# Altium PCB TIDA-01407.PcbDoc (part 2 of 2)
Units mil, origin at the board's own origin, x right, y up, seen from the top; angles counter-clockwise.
Board outline 6000 x 3000 mil, 4 copper layers (Top Layer, Signal Layer 1, Signal Layer 2, Bottom Layer), stack 79.834 mil thick; 145 components, 63 nets, 415 pads, 195 vias.
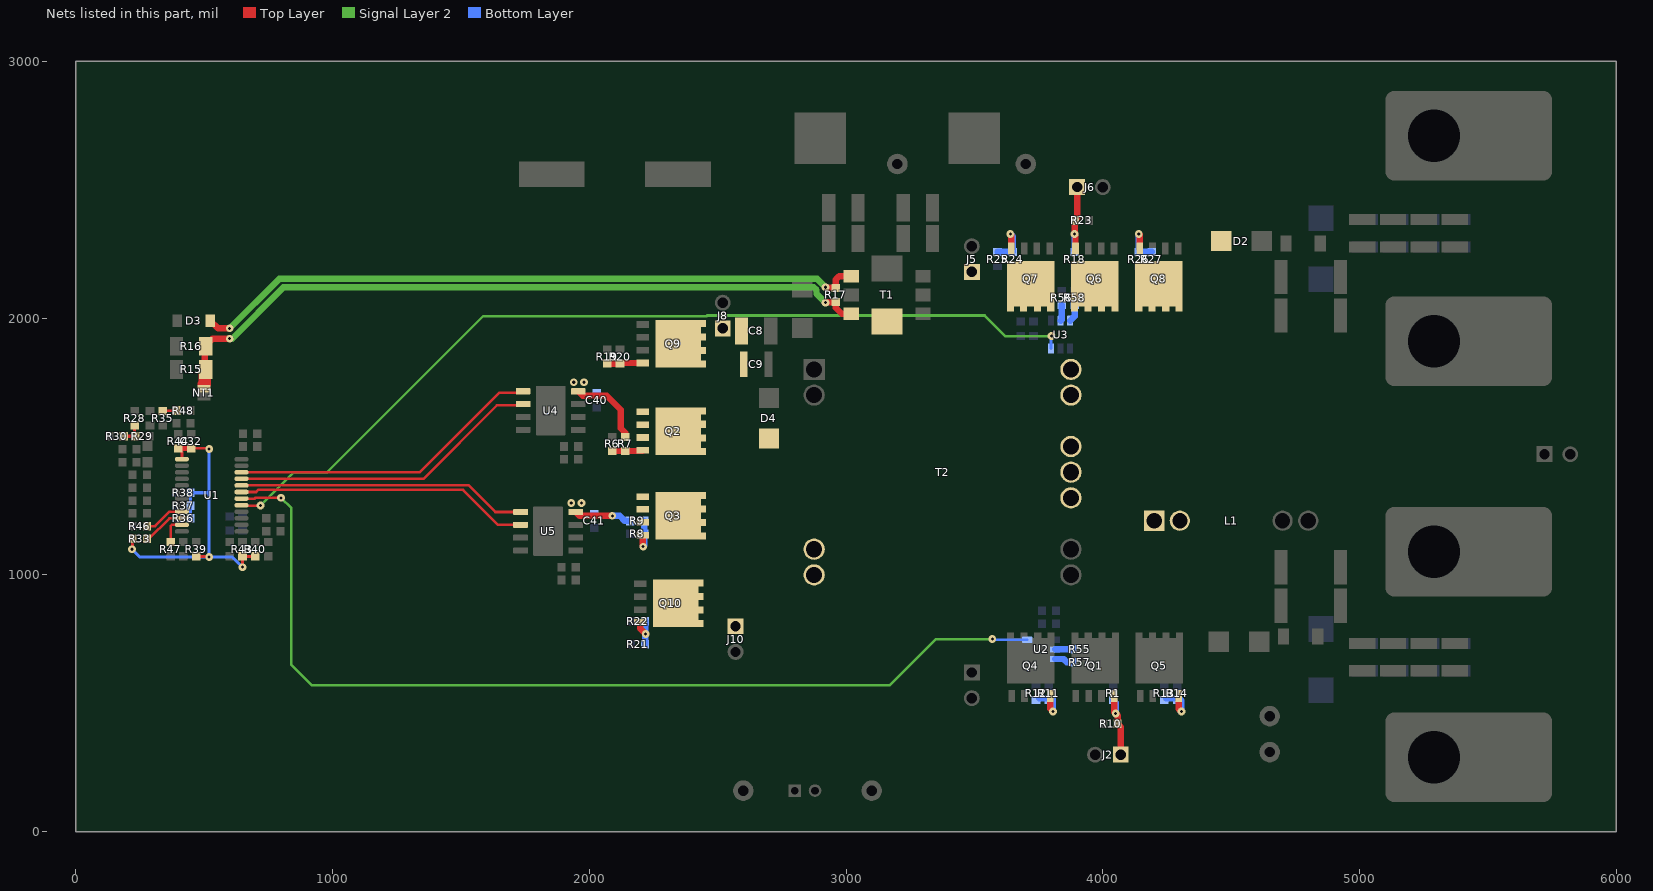
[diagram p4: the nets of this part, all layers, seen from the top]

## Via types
v1: diameter 30, hole 12, Top Layer to Bottom Layer, 177 vias
v2: diameter 19.68, hole 7.87, Top Layer to Bottom Layer, tented both sides, 8 vias
v3: diameter 19.68, hole 7.87, Top Layer to Bottom Layer, 8 vias
v4: diameter 34, hole 16, Top Layer to Bottom Layer, 2 vias

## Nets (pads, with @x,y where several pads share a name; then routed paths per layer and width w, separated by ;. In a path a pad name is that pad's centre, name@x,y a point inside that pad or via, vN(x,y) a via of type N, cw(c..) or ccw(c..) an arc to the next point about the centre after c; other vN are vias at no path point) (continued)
NetD2_2: D2.2 J5.1 Q6.5 Q6.6 Q6.7 Q6.8 Q6.9 Q7.5 Q7.6 Q7.7 Q7.8 Q7.9 Q8.5 Q8.6 Q8.7 Q8.8 Q8.9 T2.17 T2.18
NetD3_2: D3.2 R17.2 T1.1 | length 2640
  Top Layer w25: D3.2@524.47,1990 554.47,1960 v1(600,1960) ; v1(2920,2120) 2922.44,2117.56 R17.2@2960,2117.56 2960,2150 2973,2163 T1.1@3020,2163
  Signal Layer 2 w25: v1(600,1960) 792.5,2152.5 2887.5,2152.5 v1(2920,2120)
NetD4_1: D4.1 Q2.5 Q2.6 Q2.7 Q2.8 Q2.9 Q3.5 Q3.6 Q3.7 Q3.8 Q3.9 T1.7
NetJ2_1: J2.1 Q1.4 R1.1 R10.2 | length 295.7
  Top Layer w25: Q1.4@4045,528.78 4045,465 v1(4050,460) 4057.56,452.44 R10.2@4057.56,420 4070,407.56 J2.1@4070,300
  Bottom Layer w25: R1.1@4040,512.44 4050,502.44 v1(4050,460)
NetJ6_1: J6.1 Q6.4 R18.1 R23.2 | length 306.8
  Top Layer w25: Q6.4@3893.54,2271.22 3893.54,2323.79 v1(3890,2327.33) 3890.98,2328.31 R23.2@3890.98,2380 3900,2389.02 J6.1@3900,2510
  Bottom Layer w25: R18.1@3890,2264.89 v1(3890,2327.33)
NetL1_1: L1.1 L1.2 T2.13 T2.14 T2.15
NetNT1_2: NT1.2 R15.1 R16.1 R17.1 T1.3 | length 2827
  Top Layer w25: R15.1@503.15,1800 503.15,1890 533.15,1920 v1(600,1920) ; v1(2920,2060) 2922.44,2062.44 R17.1@2960,2062.44 2960,2040 2983,2017 T1.3@3020,2017
  Top Layer w50: 500,1742.5 503.15,1745.65 R15.1@503.15,1800
  Signal Layer 2 w25: v1(600,1920) 609.5,1920 809.5,2120 2874.04,2120 2885,2109.04 2885,2095 v1(2920,2060)
NetQ2_4: Q2.4 R6.2 R7.2 | length 119.8
  Top Layer w25: R6.2@2090,1482.44 R7.2@2140,1482.44 2206.22,1482.44 Q2.4@2208.78,1485
NetQ3_4: Q3.4 R8.2 R9.2 | length 147.6
  Top Layer w25: Q3.4@2208.78,1155 2208.78,1111.22 v1(2210,1110)
  Bottom Layer w25: v1(2210,1110) 2215.12,1115.12 R8.2@2215.12,1160 R9.2@2215.12,1210
NetQ4_4: Q4.4 R11.2 R12.2 | length 169.2
  Top Layer w25: Q4.4@3795,528.78 3795,479.14 v1(3806.19,467.95)
  Bottom Layer w25: R12.2@3753.16,520.39 3803.16,520.39 3806.19,517.36 v1(3806.19,467.95)
NetQ5_4: Q5.4 R13.2 R14.2 | length 172
  Top Layer w25: Q5.4@4295,528.78 4295,479.14 v1(4306.19,467.95)
  Bottom Layer w25: R13.2@4246.19,520.39 4296.19,520.39 4306.19,510.39 v1(4306.19,467.95)
NetQ7_4: Q7.4 R24.2 R25.2 | length 191.5
  Top Layer w25: v1(3640,2327.33) 3643.54,2323.79 Q7.4@3643.54,2271.22
  Bottom Layer w25: R25.2@3590,2257.56 R24.2@3650,2257.56 3650,2317.33 v1(3640,2327.33)
NetQ8_4: Q8.4 R26.2 R27.2 | length 177.3
  Top Layer w25: v1(4140,2327.33) 4143.54,2323.79 Q8.4@4143.54,2271.22
  Bottom Layer w25: v1(4140,2327.33) R26.2@4140,2257.56 R27.2@4190,2257.56
NetQ9_4: Q9.4 R19.2 R20.2 | length 139.8
  Top Layer w25: R19.2@2070,1822.44 R20.2@2120,1822.44 2122.56,1825 Q9.4@2208.78,1825
NetQ10_4: Q10.4 R21.2 R22.2 | length 145.8
  Top Layer w25: Q10.4@2198.78,815 2198.78,791.22 v1(2220,770)
  Bottom Layer w25: R21.2@2217.56,730 2217.56,767.56 v1(2220,770) 2217.56,772.44 R22.2@2217.56,820
NetR28_1: R28.1 R29.2 R30.1 | length 88.3
  Top Layer w12: R30.1@187.56,1540 R29.2@232.44,1540 230,1542.44 R28.1@230,1582.44
NetR33_1: R33.1 U1.10 | length 169.6
  Top Layer w10: R33.1@277.56,1140 284.75,1140 365.18,1220.43 U1.10@413.86,1220.43
NetR35_1: R35.1 R48.2 | length 53.5
  Top Layer w10: R35.1@340,1637.56 342.44,1640 R48.2@392.44,1640
NetR46_2: R46.2 U1.9 | length 159.5
  Top Layer w10: R46.2@277.56,1190 310,1190 366.02,1246.02 U1.9@413.86,1246.02
NetR47_2: R47.2 U1.11 | length 108.3
  Top Layer w10: R47.2@370,1127.56 370,1190 374.84,1194.84 U1.11@413.86,1194.84
NetR55_2: R55.2 U2.2 | length 64.4
  Bottom Layer w25: U2.2@3814.13,710 R55.2@3878.5,710
NetR56_2: R56.2 U3.2 | length 62.8
  Bottom Layer w25: U3.2@3835.67,1989.94 3840,1994.27 R56.2@3840,2050.94
NetR57_2: R57.2 U2.3 | length 69.6
  Bottom Layer w25: U2.3@3814.13,672.6 3847.2,672.6 3859.8,660 R57.2@3878.5,660
NetR58_2: R58.2 U3.3 | length 68
  Bottom Layer w25: U3.3@3873.07,1989.94 3890,2006.87 R58.2@3890,2050.94
PWMA: U1.22 U4.5 | length 1227.2
  Top Layer w10: U1.22@646.14,1399.57 1339.57,1399.57 1650,1710 1690,1710 1737.72,1710 U4.5@1742.72,1715
PWMB: U1.21 U4.6 | length 1217.1
  Top Layer w10: U1.21@646.14,1373.98 1353.98,1373.98 1640,1660 1690,1660 1737.72,1660 U4.6@1742.72,1665
PWMC: U1.20 U5.5 | length 1129.4
  Top Layer w10: U1.20@646.14,1348.39 1531.61,1348.39 1635,1245 U5.5@1732.72,1245
PWMD: U1.19 U5.6 | length 1146.2
  Top Layer w10: U1.19@646.14,1322.8 702.8,1322.8 710.89,1330.89 1509.11,1330.89 1645,1195 U5.6@1732.72,1195
PWME: U1.18 U2.6 | length 3796.2
  Top Layer w10: U1.18@646.14,1297.2 697.2,1297.2 700,1300 v1(800,1300)
  Signal Layer 2 w10: v1(800,1300) 840,1260 840,650 920,570 3170,570 3350,750 v1(3570,750)
  Bottom Layer w10: v1(3570,750) 3572.6,747.4 U2.6@3705.87,747.4
PWMF: U1.17 U3.6 | length 3543.2
  Top Layer w10: U1.17@646.14,1271.61 647.76,1270 v1(720,1270)
  Signal Layer 2 w10: v1(720,1270) 850,1400 980,1400 1587.5,2007.5 2457.5,2007.5 2460,2010 3540,2010 3620,1930 v1(3800,1930)
  Bottom Layer w10: U3.6@3798.27,1881.67 3798.27,1928.27 v1(3800,1930)
SW_AB: C8.1 C9.2 C40.2 J8.1 Q2.1 Q2.2 Q2.3 Q9.5 Q9.6 Q9.7 Q9.8 Q9.9 R7.1 U4.4 | length 308
  Top Layer w25: U4.4@1957.28,1715 1974.78,1697.5 2068.46,1697.5 2122.5,1643.46 2122.5,1570.81 2140,1553.31 R7.1@2140,1537.56
  other v1: 1940,1750 1980,1750
SW_CD: C41.2 J10.1 Q3.1 Q3.2 Q3.3 Q10.5 Q10.6 Q10.7 Q10.8 Q10.9 R9.1 T2.8 T2.9 U5.4 | length 227.2
  Top Layer w25: U5.4@1947.28,1245 1962.28,1230 v1(2090,1230)
  Bottom Layer w25: v1(2090,1230) 2119.23,1230 2139.23,1210 R9.1@2160,1210
  other v1: 1930,1280 1970,1280
VREF: C32.1 R33.2 R36.2 R37.2 R38.2 R39.2 R40.2 R43.2 R44.2 U1.1 | length 1404.3
  Top Layer w10: C32.1@450,1492.44 517.56,1492.44 v1(520,1490)
  Top Layer w12: v1(220,1100) 222.44,1102.44 R33.2@222.44,1140 ; R44.2@400,1492.44 413.86,1478.58 U1.1@413.86,1450.75 ; R39.2@470,1072.44 517.56,1072.44 v1(520,1070) ; v1(650,1030) R43.2@650,1072.44 R40.2@700,1072.44
  Top Layer w20: R44.2@400,1492.44 C32.1@450,1492.44
  Bottom Layer w12: v1(220,1100) 250,1070 v1(520,1070) ; R36.2@447.56,1220 R37.2@447.56,1270 R38.2@447.56,1320 520,1320 ; v1(520,1490) 520,1320 ; v1(650,1030) 610,1070 v1(520,1070) ; v1(520,1070) 520,1320
pads on no net: T1.2 T1.4 T1.5 T1.6 U1.16 U4.9@1850,1640 U5.9@1840,1170

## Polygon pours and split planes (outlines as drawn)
SW_CD on Top Layer "TOP_LAYER_SW_CD_P006" (solid, remove dead copper, pour order 6): 1993.27,1235.09 1913.27,1235.09 1913.27,1305.09 1993.27,1305.09
SW_AB on Top Layer "TOP_LAYER_SW_AB_P002" (solid, remove dead copper, pour order 2): 1920,1770 1920,1700 2000,1700 2000,1770
GND on Top Layer "TOP_LAYER_GND_P046" (solid, remove dead copper, pour order 46): 100,2900 100,100 5900,100 5900,2900
NetC6_1 on Top Layer "TOP_LAYER_NETC6_1_P040" (solid, remove dead copper, pour order 40): 4570,1940 4740,1940 4740,2340 4570,2340
SW_AB on Top Layer "TOP_LAYER_SW_AB_P038" (solid, remove dead copper, pour order 38): 2630,1640 2510,1640 2500,1650 2480,1670 2240,1670 2240,1520 2090,1520 2090,1640 2170,1720 2170,1740 2250,1820 2250,2000 2630,2000
SW_CD on Top Layer "TOP_LAYER_SW_CD_P036" (solid, remove dead copper, pour order 36): 2240,1370 2100,1370 2100,1052.26 2240,912.26 2240,770 3260,770 3260,1150 2540,1150 2510,1120 2240,1120
NetC6_2 on Top Layer "TOP_LAYER_NETC6_2_P034" (solid, remove dead copper, pour order 34): 4420,1170 4570,1170 4570,1120 4750,1120 4750,700 5900,700 5900,2320 4760,2320 4760,1920 4570,1920 4570,1630 4420,1630
NetC6_1 on Top Layer "TOP_LAYER_NETC6_1_P032" (solid, remove dead copper, pour order 32): 4570,690 4730,690 4730,1100 4570,1100
NetC1_1 on Top Layer "TOP_LAYER_NETC1_1_P030" (solid, remove dead copper, pour order 30): 2100,2500 2100,2900 3300,2900 3300,2300 3230,2230 3230,2130 3090,2130 3090,2170 3000,2260 3000,2500
NetD4_1 on Top Layer "TOP_LAYER_NETD4_1_P028" (solid, remove dead copper, pour order 28): 3060,2040 3060,1650 3040,1630 2500,1630 2470,1660 2250,1660 2250,1130 2500,1130 2530,1160 3260,1160 3260,2040
NetC8_2 on Top Layer "TOP_LAYER_NETC8_2_P026" (solid, remove dead copper, pour order 26): 2650,1640 3040,1640 3040,2000 2650,2000
NetD1_2 on Top Layer "TOP_LAYER_NETD1_2_P020" (solid, remove dead copper, pour order 20): 3400,570 3400,1150 4550,1150 4550,570
NetD2_2 on Top Layer "TOP_LAYER_NETD2_2_P016" (solid, remove dead copper, pour order 16): 3400,1650 3400,2230 4420,2230 4420,2340 4550,2340 4550,2230 4550,1650
NetL1_1 on Top Layer "TOP_LAYER_NETL1_1_P012" (solid, remove dead copper, pour order 12): 3400,1170 3400,1630 4400,1630 4400,1170
GND on Signal Layer 1 "SIGNAL_LAYER_1_GND_P048" (solid, remove dead copper, pour order 48): 100,2900 100,100 5900,100 5900,2900
NetD1_2 on Signal Layer 1 "SIGNAL_LAYER_1_NETD1_2_P022" (solid, remove dead copper, pour order 22): 3400,570 3400,1150 4550,1150 4550,570
NetD2_2 on Signal Layer 1 "SIGNAL_LAYER_1_NETD2_2_P018" (solid, remove dead copper, pour order 18): 3400,1650 3400,2230 4550,2230 4550,1650
NetL1_1 on Signal Layer 1 "SIGNAL_LAYER_1_NETL1_1_P014" (solid, remove dead copper, pour order 14): 3400,1170 3400,1630 4550,1630 4550,1170
NetC6_1 on Signal Layer 1 "SIGNAL_LAYER_1_NETC6_1_P044" (solid, remove dead copper, pour order 44): 4570,820 4650,820 4650,2230 4570,2230
NetC41_1 on Bottom Layer "BOTTOM_LAYER_NETC41_1_P000" (solid, remove dead copper, pour order 0): 2050,1120 2050,1200 1970,1200 1970,1120
SW_CD on Bottom Layer "BOTTOM_LAYER_SW_CD_P004" (solid, remove dead copper, pour order 4): 2040,1220 2040,1300 1900,1300 1900,1220
NetC40_1 on Bottom Layer "BOTTOM_LAYER_NETC40_1_P008" (solid, remove dead copper, pour order 8): 2060,1670 2060,1590 1980,1590 1980,1670
SW_AB on Bottom Layer "BOTTOM_LAYER_SW_AB_P010" (solid, remove dead copper, pour order 10): 2050,1770 2050,1690 1910,1690 1910,1770
GND on Bottom Layer "BOTTOM_LAYER_GND_P052" (solid, remove dead copper, pour order 52): 100,2900 100,107.5 103.75,103.75 5896.25,103.75 5900,100 5900,2900
NetC6_2 on Bottom Layer "BOTTOM_LAYER_NETC6_2_P042" (solid, remove dead copper, pour order 42): 5900,2320 4600,2320 4600,700 5900,700
GND on Signal Layer 2 "SIGNAL_LAYER_2_GND_P050" (solid, remove dead copper, pour order 50): 100,2900 100,100 5900,100 5900,2900

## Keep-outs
Keep-Out Layer:
  lines w10: -5,0 ccw(c0,0) 0,-5 ; -5,0 ccw(c0,0) 0,-5 ; -5,0 -5,3000 ; -5,3000 cw(c0,3000) 0,3005 ; -5,3000 cw(c0,3000) 0,3005 ; 0,-5 6000,-5 ; 0,3005 6000,3005 ; 6000,-5 ccw(c6000,0) 6005,0 ; 6000,-5 ccw(c6000,0) 6005,0 ; 6000,3005 cw(c6000,3000) 6005,3000 ; 6000,3005 cw(c6000,3000) 6005,3000 ; 6005,0 6005,3000
  text ".Layer_Name" at 577,-858.49 h60

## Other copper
Top Layer:
  text ".Layer_Name" at 577,-858.49 h60
Bottom Layer:
  text ".Layer_Name" at 577,-858.49 h60

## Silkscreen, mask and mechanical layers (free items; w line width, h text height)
Top Overlay:
  region: 2300,310 2000,310 2000,210 2300,210
  text "GATE_F" at 3860,2610 h25
  text "GND" at 3980,2610 h25
  text "VOUT" at 5690,1540 h25
  text "GND" at 5790,1540 h25
  text "'.PRJ_Number'.PCB_Rev-" at 1420,230 h108.27
  text "GND" at 3940,220 h25
  text "GATE_E" at 4030,220 h25
  text "VDD" at 2570,70 h25
  text "GND" at 3070,70 h25
  text ".Layer_Name" at 577,-858.49 h60
Bottom Overlay:
  text ".Layer_Name" at 577,-858.49 h60
Top Paste:
  text ".Layer_Name" at 577,-858.49 h60
Bottom Paste:
  text ".Layer_Name" at 577,-858.49 h60
Top Solder:
  text ".Layer_Name" at 577,-858.49 h60
  text ".Layer_Name" at 577,-858.49 h60
Bottom Solder:
  text ".Layer_Name" at 577,-858.49 h60
Drill Guide:
  text ".Layer_Name" at 577,-858.49 h60
M1 Board Outline:
  the board outline again, w10
  text ".Layer_Name" at 577,-858.49 h60
M2 Board Dimensions:
  rectangle: 0,-275 125,-150
  rectangle: 125,-400 500,-275
  lines w7: 0,-275 1000,-275 ; 125,-400 125,-150 ; 250,-400 250,-150 ; 500,-400 500,-150 ; 750,-400 750,-150 ; 0,-400 1000,-400 1000,-150 0,-150 0,-400
  text ".Layer_Name" at 577,-858.49 h60
M3 3D STEP Top:
  text ".Layer_Name" at 577,-858.49 h60
M4 3D STEP Bottom:
  text ".Layer_Name" at 577,-858.49 h60
M5 Assembly Top:
  lines w10: -292,-930.17 6308,-930.17 ; -292,-726.83 6310,-726.83 ; -292,-523.5 -292,-1133.5 3713,-1133.5 6310,-1133.5 6310,-523.5 -291.5,-523.5 -291.5,-1133.5 1284,-1133.5 ; 2173,-1133.5 2173,-523.5 ; 3440,-726.83 3440,-523.5 ; 4280,-726.83 4280,-523.5 ; 4902,-1140 4902,-937.17
  text "COMPONENTS MARKED 'DNP' SHOULD NOT BE POPULATED." at 1153.5,-318.5 h60
  text "ASSEMBLY VARIANT:" at 1153,-434 h60
  text ".VariantName" at 2189,-434 h60
  text "PCB VIEWED FROM TOP SIDE" at -228.5,-655.67 h60
  text "BOARD #:" at 2248,-655.67 h60
  text ".PRJ_Number" at 2793.5,-655.67 h60
  text "REV:" at 3638,-655.67 h60
  text ".PCB_Rev" at 3929.5,-655.67 h60
  text "SVN REV:" at 4476,-655.67 h60
  text ".VersionControl_RevNumber" at 4982,-655.67 h60
  text "TID #:" at 2248,-859 h60
  text ".TID" at 2793.5,-859 h60
  text "PLOT NAME =" at -228.5,-1064.34 h60
  text ".plot_File_Name" at 577,-1064.34 h60
  text "GENERATED    :" at 2250,-1064.34 h60
  text ".Print_Date" at 3119.5,-1064.34 h60
  text ".Print_Time" at 3848.5,-1064.34 h60
  text "TEXAS INSTRUMENTS" at 5113,-1064.34 h60
M6 Assembly Bottom:
  lines w10: -292.5,-727.33 6309.5,-727.33 ; -290.5,-930.67 6309.5,-930.67 ; 1115.5,-1140.5 1115.5,-937.67 ; 1737.5,-727.33 1737.5,-524 ; 2577.5,-727.33 2577.5,-524 ; 3844.5,-1134 3844.5,-524 ; 4733.5,-1134 6309,-1134 6309,-524 -292.5,-524 -292.5,-1134 2304.5,-1134 6309.5,-1134 6309.5,-524
  text "COMPONENTS MARKED 'DNP' SHOULD NOT BE POPULATED." at 6102,-318 h60
  text ".VariantName" at 5058,-434 h60
  text "ASSEMBLY VARIANT:" at 6097,-434 h60
  text ".VersionControl_RevNumber" at 1035.5,-656.17 h60
  text "SVN REV:" at 1541.5,-656.17 h60
  text ".PCB_Rev" at 2088,-656.17 h60
  text "REV:" at 2379.5,-656.17 h60
  text ".PRJ_Number" at 3224,-656.17 h60
  text "BOARD #:" at 3769.5,-656.17 h60
  text "PCB VIEWED FROM BOTTOM SIDE" at 6246,-656.17 h60
  text ".TID" at 3224,-859.5 h60
  text "TID #:" at 3769.5,-859.5 h60
  text "TEXAS INSTRUMENTS" at 904.5,-1064.84 h60
  text ".Print_Time" at 2169,-1064.84 h60
  text ".Print_Date" at 2898,-1064.84 h60
  text "GENERATED    :" at 3767.5,-1064.84 h60
  text ".plot_File_Name" at 5440.5,-1064.84 h60
  text "PLOT NAME =" at 6246,-1064.84 h60
M9 Title Sheet:
  drawing of 57 lines, arcs and shapes, not listed
  text "1" at 739.84,8036.5 h70
  text "2" at 3235.5,8036.5 h70
  text "3" at 5724.84,8036.5 h70
  text "4" at 8231.51,8036.5 h70
  text "5" at 10730.5,8036.5 h70
  text "6" at 13235.5,8036.5 h70
  text "A" at -416.5,6893.5 h70
  text "A" at 14383.5,6893.5 h70
  text "B" at -416.5,4513.5 h70
  text "B" at 14383.5,4513.5 h70
  text "C" at -416.5,2138.5 h70
  text "C" at 14383.5,2138.5 h70
  text "PROJECT TITLE:" at 11343.5,277.5 h45
  text ".PRJ_Title" at 11393.5,144.17 h70
  text "DESIGNED FOR:" at 11343.5,-23.5 h45
  text ".PRJ_Customer" at 11393.5,-163.5 h70
  text "D" at -416.5,-231.5 h70
  text "D" at 14383.5,-231.5 h70
  text "FILE NAME:" at 11343.5,-323.5 h45
  text ".PCB_File_Name_No_Path" at 11393.5,-443.5 h70
  text "Texas Instruments (TI) and/or its licensors do not warrant the accuracy or completeness of this specification" at 6374,-605.34 h45
  text "ENGINEER:" at 11343.5,-613.5 h45
  text "LAYOUT BY:" at 12848.5,-613.5 h45
  text "or any information contained therein. TI and/or its licensors do not warrant that this design will meet" at 6329.01,-718 h45
  text ".PRJ_Engineer" at 11393.5,-768.49 h70
  text ".PCB_Layout" at 12899,-768.49 h70
  text "the specifications, will be suitable for your application or fit for any particular purpose, or will operate in" at 6329.01,-830.67 h45
  text ".Layer_Name" at 577,-858.49 h60
  text "ALTIUM DESIGNER VERSION:" at 12848.5,-923.5 h45
  text "an implementation. TI and/or its licensors do not warrant that the design is production worthy. You should" at 6329.01,-943.33 h45
  text "completely validate and test your design implementation to confirm the system functionality for your application." at 6374,-1056 h45
  text ".print_Scale" at 11393.5,-1056.83 h70
  text ".Application_BuildNumber" at 12899,-1056.83 h70
  text "1" at 739.84,-1263.5 h70
  text "2" at 3235.5,-1263.5 h70
  text "3" at 5724.84,-1263.5 h70
  text "4" at 8231.51,-1263.5 h70
  text "5" at 10730.5,-1263.5 h70
  text "6" at 13235.5,-1263.5 h70
M10 Fab Notes:
  drawing of 173 lines, arcs and shapes, not listed
  text "DESIGN INFORMATION" at 12378.02,6201 h60
  text "MIN. TRACK WIDTH:" at 11733.46,6021 h60
  text "8" at 12829.7,6021 h60
  text "MIL" at 12984.46,6021 h60
  text "MIN. CLEARANCE:" at 11733.46,5889 h60
  text "0.2" at 12769.7,5889 h60
  text "mm" at 12984.46,5889 h60
  text "MIN. VIA PAD SIZE:" at 11733.46,5757 h60
  text "24" at 12799.71,5757 h60
  text "MIL" at 12984.46,5757 h60
  text "0.05mm (2MIL)" at 12428.46,5615.29 h60
  text "MINIMUM ANNULAR RING" at 11404.23,5611 h60
  text "EXTERNAL" at 13136.46,5611 h60
  text "PER" at 11604.23,5493 h60
  text "IPC-D-275 CLASS 2 LEVEL C" at 11824.23,5493 h60
  text "MIL, HOLES" at 13312.46,5380.71 h60
  text "+/-" at 12920,5380 h60
  text "+/-" at 13774,5380 h60
  text "REGISTRATION TOLERANCES:" at 11404.23,5375 h60
  text "METAL" at 12604,5375 h60
  text "5" at 13180.2,5375 h60
  text "3" at 14013.2,5375 h60
  text "MIL" at 14129.46,5375 h60
  text "+/-" at 13774,5262 h60
  text "HOLE SIZE TOLERANCE (UNLESS OTHERWISE SPECIFIED):" at 11404.23,5257 h60
  text "3" at 14013.2,5257 h60
  text "MIL" at 14129.46,5257 h60
  text "MATERIAL:" at 11329.46,5047.54 h60
  text "FR-4 High Tg" at 12315.9,4907.21 h60
  text "FR-408" at 11750.46,4898.64 h60
  text "OTHER" at 13238.46,4898.64 h60
  text "X" at 12161,4895 h60
  text "62 MIL (1.6mm) +/-10%" at 12070.56,4735.92 h60
  text "THICKNESS:" at 11404.23,4731.64 h60
  text "X" at 11942.4,4731.64 h60
  text "OTHER" at 13355.46,4731.64 h60
  text "TOLERANCE:" at 11404.23,4573.64 h60
  text "X" at 12243.53,4573.64 h60
  text "ANSI IPC-6012 TYPE 3 CLASS 2" at 12430.48,4573.64 h60
  text "OTHER +/-" at 12430.46,4417.64 h60
  text "BOW & TWIST:" at 11404.23,4260.64 h60
  text "X" at 12243.53,4260.64 h60
  text "ANSI IPC-6012 TYPE 3 CLASS 2" at 12430.48,4260.64 h60
  text "OTHER +/-" at 12430.46,4102.13 h60
  text "DRILLING:" at 11329.46,3963.64 h60
  text "REFERENCE:" at 11404.23,3846.64 h60
  text "X" at 12052.46,3846.64 h60
  text "AS SHOWN" at 12239.46,3846.64 h60
  text "X" at 12953.46,3846.64 h60
  text "NC_DRILL FILES" at 13090.46,3846.64 h60
  text "PTH COPPER THICKNESS:" at 11404.23,3688.64 h60
  text "X" at 12534.46,3688.64 h60
  text "20-30 um" at 12671.46,3688.64 h60
  text "OTHER" at 13388.46,3688.64 h60
  text "BOARD FINISH:" at 11329.46,3529.64 h60
  text "SILKSCREEN:" at 11484.68,3411.64 h60
  text "X" at 12433.46,3411.64 h60
  text "TOP" at 12559.46,3411.64 h60
  text "X" at 12943.46,3411.64 h60
  text "BOTTOM" at 13070.46,3411.64 h60
  text "SILKSCREEN COLOR:" at 11484.68,3244.64 h60
  text "X" at 12432.42,3244.64 h60
  text "WHITE" at 12559.46,3244.64 h60
  text "OTHER" at 13070.46,3244.64 h60
  text "X" at 12563.42,3085.44 h60
  text "GREEN" at 12690.46,3085.44 h60
  text "OTHER" at 13308.46,3085.44 h60
  text "SOLDER RESIST COLOR:" at 11484.68,3074.64 h60
  text "X" at 12563.42,2915.44 h60
  text "MATTE" at 12690.46,2915.44 h60
  text "SEMI-GLOSS" at 13308,2914.8 h60
  text "IMMERSION GOLD (ENIG)" at 12390.46,2726.92 h60
  text "ENEPIG" at 13728,2723.64 h60
  text "SURFACE FINISH:" at 11329.46,2722.64 h60
  text "X" at 12203.51,2722.64 h60
  text "IMM. TIN/SILVER OR EQUIV" at 11659,2565.64 h60
  text "OTHER" at 13090.46,2565.64 h60
  text "ARRAY/PANEL:" at 11329.46,2386.64 h60
  text "CUT AND TRIM PER M1 BOARD OUTLINE" at 12390.46,2382.35 h60
  text "N.C. ROUTE" at 12390.46,2230.64 h60
  text "X" at 13069.46,2230.64 h60
  text "V. SCORE" at 13256.46,2230.64 h60
  text "CERTIFICATION:" at 11329.46,2093.64 h60
  text "MATERIALS AND WORKMANSHIP FOR ALL PCBS" at 12054.46,2093.64 h60
  text "TO MEET OR EXCEED THE REQUIREMENTS OF:" at 12054.46,1995.64 h60
  text "X" at 11680.96,1859.13 h60
  text "ANSI IPC-A-600F CLASS ->" at 11819.96,1859.13 h60
  text "X" at 13459.02,1859.13 h60
  text "2" at 13577.96,1859.14 h60
  text "1" at 13262.96,1857.64 h60
  text "3" at 13931.96,1857.64 h60
  text "X" at 12495.02,1699.64 h60
  text "RoHS" at 12631.96,1699.64 h60
  text "OTHER" at 13276.36,1699.64 h60
  text "PER ORDER" at 13673.42,1699.64 h60
  text "ALL BOARDS MUST MEET OR EXCEED UL94-V0 REQUIREMENTS." at 11357,1534 h60
  text "PCB MUST BEAR THE UL94V-0 UL REGISTERED MATERIAL ID NUMBER" at 11357,1414 h60
  text "ADDITIONAL REQUIREMENTS:" at 11329.46,1240.64 h60
  text "MICROSECTION:" at 11404.23,1125.64 h60
  text "YES" at 12309.96,1125.64 h60
  text "REQUIRED" at 13171.46,969.49 h60
  text "BARE BOARD ELEC. TEST:" at 11404.23,966.64 h60
  text "NONE" at 12709.96,966.64 h60
  text "X" at 13044.46,966.64 h60
  text "PER ORDER" at 13763.46,966.64 h60
  text ".Layer_Name" at 577,-858.49 h60
M11 Gerber Information:
  lines w10: -292,-930.17 6308,-930.17 ; -292,-726.83 6310,-726.83 ; -292,-523.5 -292,-1133.5 3713,-1133.5 6310,-1133.5 6310,-523.5 -291.5,-523.5 -291.5,-1133.5 1284,-1133.5 ; 2173,-1133.5 2173,-523.5 ; 3440,-726.83 3440,-523.5 ; 4280,-726.83 4280,-523.5 ; 4902,-1140 4902,-937.17
  text "ALL ARTWORK VIEWED FROM TOP SIDE" at -228.5,-655.67 h60
  text "BOARD #:" at 2248,-655.67 h60
  text ".PRJ_Number" at 2793.5,-655.67 h60
  text "REV:" at 3638,-655.67 h60
  text ".PCB_Rev" at 3929.5,-655.67 h60
  text "SVN REV:" at 4476,-655.67 h60
  text ".VersionControl_RevNumber" at 4982,-655.67 h60
  text "LAYER NAME =" at -228.5,-858.49 h60
  text "TID #:" at 2248,-859 h60
  text ".TID" at 2793.5,-859 h60
  text "PLOT NAME =" at -228.5,-1064.34 h60
  text ".plot_File_Name" at 577,-1064.34 h60
  text "GENERATED    :" at 2250,-1064.34 h60
  text ".Print_Date" at 3119.5,-1064.34 h60
  text ".Print_Time" at 3848.5,-1064.34 h60
  text "TEXAS INSTRUMENTS" at 5113,-1064.34 h60
M12 Stackup:
  drawing of 295 lines, arcs and shapes, not listed
  text "Layer" at 9710.09,7770 h60
  text "Name" at 10120,7770 h60
  text "Material" at 11059.74,7770 h60
  text "Thickness" at 11919.51,7770 h60
  text "Constant" at 12569.34,7770 h60
  text "Board Layer Stack" at 13139.2,7770 h60
  text "1" at 9710.09,7650 h60
  text "Top Overlay" at 10120,7650 h60
  text "2" at 9710.09,7530 h60
  text "Top Solder" at 10120,7530 h60
  text "Solder Resist" at 11059.74,7530 h60
  text "0.40mil" at 11919.51,7530 h60
  text "3.5" at 12569.34,7530 h60
  text "3" at 9710.09,7410 h60
  text "Top Layer" at 10120,7410 h60
  text "Copper" at 11059.74,7410 h60
  text "1.40mil" at 11919.51,7410 h60
  text "4" at 9710.09,7290 h60
  text "Dielectric1" at 10120,7290 h60
  text "FR-4" at 11059.74,7290 h60
  text "59.20mil" at 11919.51,7290 h60
  text "4.8" at 12569.34,7290 h60
  text "5" at 9710.09,7170 h60
  text "Signal Layer 1" at 10120,7170 h60
  text "Copper" at 11059.74,7170 h60
  text "1.42mil" at 11919.51,7170 h60
  text "6" at 9710.09,7050 h60
  text "Dielectric 3" at 10120,7050 h60
  text "5.00mil" at 11919.51,7050 h60
  text "4.2" at 12569.34,7050 h60
  text "7" at 9710.09,6930 h60
  text "Signal Layer 2" at 10120,6930 h60
  text "Copper" at 11059.74,6930 h60
  text "1.42mil" at 11919.51,6930 h60
  text "8" at 9710.09,6810 h60
  text "Dielectric 2" at 10120,6810 h60
  text "10.00mil" at 11919.51,6810 h60
  text "4.2" at 12569.34,6810 h60
  text "9" at 9710.09,6690 h60
  text "Bottom Layer" at 10120,6690 h60
  text "Copper" at 11059.74,6690 h60
  text "1.40mil" at 11919.51,6690 h60
  text "10" at 9710.09,6570 h60
  text "Bottom Solder" at 10120,6570 h60
  text "Solder Resist" at 11059.74,6570 h60
  text "0.40mil" at 11919.51,6570 h60
  text "3.5" at 12569.34,6570 h60
  text "11" at 9710.09,6450 h60
  text "Bottom Overlay" at 10120,6450 h60
  text ".Layer_Name" at 577,-858.49 h60
M13 Component Bodies Top:
  text ".Layer_Name" at 577,-858.49 h60
M14 Component Bodies Bottom:
  text ".Layer_Name" at 577,-858.49 h60
M15 Courtyards Top:
  text ".Layer_Name" at 577,-858.49 h60
M16 Courtyards Bottom:
  text ".Layer_Name" at 577,-858.49 h60
Drill Drawing:
  circle w10: c6743.73,1364.58 r27.63
  lines w10: 6716.1,963.95 6743.73,977.76 6771.36,963.95 6757.54,991.58 6771.36,1019.21 6743.73,1005.39 6716.1,1019.21 6729.91,991.58 6716.1,963.95 ; 6716.1,1088.28 6771.36,1088.28 6771.36,1143.54 6716.1,1143.54 6716.1,1088.28 ; 6716.1,1267.88 6771.36,1267.88 6743.73,1212.62 6716.1,1267.88 ; 6716.1,1461.29 6716.1,1475.11 6729.91,1488.92 6716.1,1502.74 6716.1,1516.55 6729.91,1516.55 6743.73,1502.74 6757.54,1516.55 6771.36,1516.55 6771.36,1502.74 6757.54,1488.92 6771.36,1475.11 6771.36,1461.29 6757.54,1461.29 6743.73,1475.11 6729.91,1461.29 6716.1,1461.29 ; 6716.1,1585.62 6771.36,1585.62 6771.36,1640.89 6716.1,1640.89 6716.1,1585.62 ; 6716.1,1723.78 6729.91,1723.78 6729.91,1709.96 6757.54,1709.96 6757.54,1723.78 6771.36,1723.78 6771.36,1751.41 6757.54,1751.41 6757.54,1765.22 6729.91,1765.22 6729.91,1751.41 6716.1,1751.41 6716.1,1723.78 ; 6716.1,1848.11 6729.91,1848.11 6743.73,1834.3 6757.54,1848.11 6771.36,1848.11 6757.54,1861.93 6771.36,1875.74 6757.54,1875.74 6743.73,1889.56 6729.91,1875.74 6716.1,1875.74 6729.91,1861.93 6716.1,1848.11 ; 6716.1,1986.26 6743.73,1958.63 6771.36,1986.26 6743.73,2013.89 6716.1,1986.26 ; 6727.15,1596.68 6760.3,1596.68 6760.3,1629.83 6727.15,1629.83 6727.15,1596.68
  lines w12: 6666,926.65 9896.06,926.65 ; 6666,2045.66 9896.06,2045.66 ; 7003.75,802.31 7003.75,2170 ; 7335.56,802.31 7335.56,2170 ; 7971.66,802.31 7971.66,2170 ; 8230.66,802.31 8230.66,2170 ; 8605.64,802.31 8605.64,2170 ; 9329.86,802.31 9329.86,2170 ; 6666,802.31 9896.06,802.31 9896.06,2170 6666,2170 6666,802.31
  text "Symbol" at 6740.6,2082.97 h72
  text "Quantity" at 7041.05,2082.97 h72
  text "Finished Hole Size" at 7372.86,2082.97 h72
  text "Plated" at 8008.96,2082.97 h72
  text "Hole Type" at 8267.96,2082.97 h72
  text "Drill Layer Pair" at 8642.94,2082.97 h72
  text "Hole Tolerance" at 9367.16,2082.97 h72
  text "16" at 7041.05,1958.63 h60
  text "7.87mil (0.200mm)" at 7372.86,1958.63 h60
  text "PTH" at 8008.96,1958.63 h60
  text "Round" at 8267.96,1958.63 h60
  text "Top Layer - Bottom Layer" at 8642.94,1958.63 h60
  text "177" at 7041.05,1834.3 h60
  text "12.00mil (0.305mm)" at 7372.86,1834.3 h60
  text "PTH" at 8008.96,1834.3 h60
  text "Round" at 8267.96,1834.3 h60
  text "Top Layer - Bottom Layer" at 8642.94,1834.3 h60
  text "2" at 7041.05,1709.96 h60
  text "16.00mil (0.406mm)" at 7372.86,1709.96 h60
  text "PTH" at 8008.96,1709.96 h60
  text "Round" at 8267.96,1709.96 h60
  text "Top Layer - Bottom Layer" at 8642.94,1709.96 h60
  text "2" at 7041.05,1585.62 h60
  text "29.53mil (0.750mm)" at 7372.86,1585.62 h60
  text "PTH" at 8008.96,1585.62 h60
  text "Round" at 8267.96,1585.62 h60
  text "Top Layer - Bottom Layer" at 8642.94,1585.62 h60
  text "13" at 7041.05,1461.29 h60
  text "40.00mil (1.016mm)" at 7372.86,1461.29 h60
  text "PTH" at 8008.96,1461.29 h60
  text "Round" at 8267.96,1461.29 h60
  text "Top Layer - Bottom Layer" at 8642.94,1461.29 h60
  text "7" at 7041.05,1336.95 h60
  text "40.16mil (1.020mm)" at 7372.86,1336.95 h60
  text "PTH" at 8008.96,1336.95 h60
  text "Round" at 8267.96,1336.95 h60
  text "Top Layer - Bottom Layer" at 8642.94,1336.95 h60
  text "4" at 7041.05,1212.62 h60
  text "59.06mil (1.500mm)" at 7372.86,1212.62 h60
  text "PTH" at 8008.96,1212.62 h60
  text "Round" at 8267.96,1212.62 h60
  text "Top Layer - Bottom Layer" at 8642.94,1212.62 h60
  text "11" at 7041.05,1088.28 h60
  text "62.99mil (1.600mm)" at 7372.86,1088.28 h60
  text "PTH" at 8008.96,1088.28 h60
  text "Round" at 8267.96,1088.28 h60
  text "Top Layer - Bottom Layer" at 8642.94,1088.28 h60
  text "4" at 7041.05,963.95 h60
  text "203.15mil (5.160mm)" at 7372.86,963.95 h60
  text "PTH" at 8008.96,963.95 h60
  text "Round" at 8267.96,963.95 h60
  text "Top Layer - Bottom Layer" at 8642.94,963.95 h60
  text "236 Total" at 7041.05,839.61 h60
  text ".Layer_Name" at 577,-858.49 h60
M17 Embedded Cavity:
  text ".Layer_Name" at 577,-858.49 h60
M18 Embedded Assembly:
  text ".Layer_Name" at 577,-858.49 h60
M19 Embedded Keepout:
  text ".Layer_Name" at 577,-858.49 h60

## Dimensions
0,-400 to 1000,-400 on M2 Board Dimensions
0,0 to 0,3000 on M2 Board Dimensions
0,0 to 6000,0 on M2 Board Dimensions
